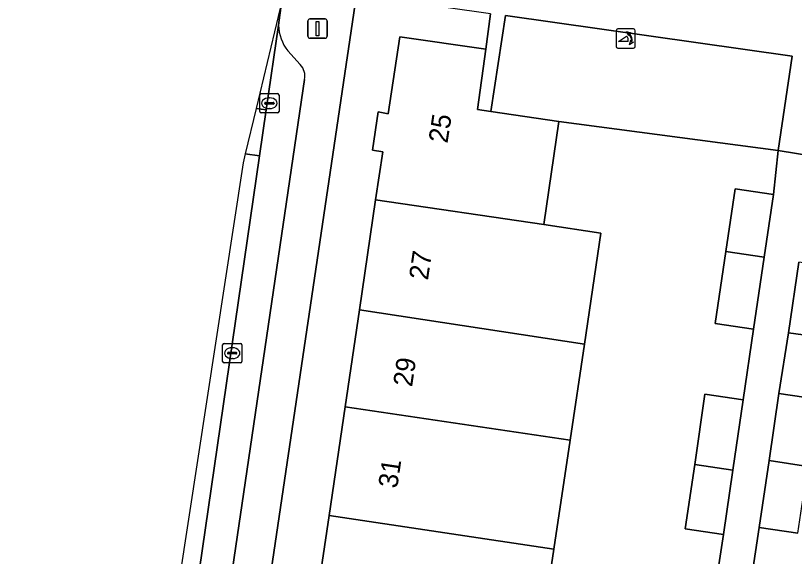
# Model space of a CAD drawing. Extents: x 164148 to 165261, y 382513 to 383432.
# Drawn here: x 164207.73 to 164248.11, y 382965.61 to 382993.68 of the extents above; entities that cross this region are included whole.
import ezdxf

# ---------------------------------------------------------------- set-up
doc = ezdxf.new("R2010")
doc.units = 0
for name, color, linetype in [('IMGEO_Erf', 7, 'Continuous'), ('IMGEO_Kolk', 7, 'Continuous'), ('IMGEO_Lichtmast', 7, 'Continuous'), ('IMGEO_Pand', 7, 'Continuous'), ('IMGEO_Pand_nummerreeks', 7, 'Continuous'), ('IMGEO_Parkeervlak_open', 7, 'Continuous'), ('IMGEO_Poller', 7, 'Continuous'), ('IMGEO_Rijbaan_lokaal_gesloten', 7, 'Continuous'), ('IMGEO_Rijbaan_lokaal_open', 7, 'Continuous'), ('IMGEO_Voetpad_open', 7, 'Continuous')]:
    doc.layers.add(name, color=color, linetype=linetype)

msp = doc.modelspace()

# ---------------------------------------------------------------- linework, layer by layer
at = {"layer": 'IMGEO_Erf'}
msp.add_lwpolyline([(164223.194, 382962.384), (164223.982, 382967.727), (164224.814, 382973.374), (164225.557, 382978.411), (164226.399, 382984.12), (164226.766, 382986.613), (164226.242, 382986.692), (164226.538, 382988.678), (164227.056, 382988.575), (164227.652, 382992.573), (164232.112, 382991.925), (164232.356, 382993.76), (164225.405, 382994.767), (164218.335, 382947.025), (164225.294, 382945.995), (164225.622, 382947.869), (164221.151, 382948.522), (164221.738, 382952.502), (164221.214, 382952.579), (164221.507, 382954.563), (164222.031, 382954.492), (164222.436, 382957.239)], close=True, dxfattribs=at)
for points in [[(164243.867, 382963.027), (164244.432, 382966.748), (164242.453, 382967.035), (164242.939, 382970.38), (164243.468, 382974.022), (164245.448, 382973.734), (164245.986, 382977.397), (164244.007, 382977.691), (164244.562, 382981.432), (164245.046, 382984.689), (164247.024, 382984.396), (164247.26, 382986.674), (164235.9, 382988.175), (164235.114, 382982.83), (164238.076, 382982.393), (164237.235, 382976.626), (164236.488, 382971.649), (164235.639, 382965.995), (164234.838, 382960.655)], [(164249.829, 382976.93), (164247.812, 382977.22), (164247.307, 382974.069), (164249.315, 382973.774)], [(164248.292, 382966.82), (164246.284, 382967.115), (164245.907, 382964.58), (164247.915, 382964.284), (164247.398, 382960.779), (164246.889, 382957.328), (164244.881, 382957.624), (164244.553, 382955.398), (164246.557, 382955.102), (164246.026, 382951.547), (164245.485, 382947.932), (164243.495, 382948.226), (164243.081, 382945.579), (164245.089, 382945.283), (164244.566, 382941.738), (164244.062, 382938.318)]]:
    msp.add_lwpolyline(points, dxfattribs=at)
at = {"layer": 'IMGEO_Kolk'}
for p, q in [((164220.388, 382988.7), (164220.388, 382989.552)), ((164220.463, 382989.626), (164221.315, 382989.626)), ((164220.876, 382989.406), (164220.901, 382989.406)), ((164221.389, 382989.552), (164221.389, 382988.7)), ((164220.647, 382989.12), (164220.647, 382989.132)), ((164221.085, 382989.083), (164220.687, 382989.083)), ((164220.69, 382989.169), (164221.088, 382989.169)), ((164220.899, 382988.846), (164220.874, 382988.846)), ((164221.131, 382989.132), (164221.131, 382989.12)), ((164221.315, 382988.626), (164220.463, 382988.626)), ((164218.462, 382975.732), (164218.462, 382976.584)), ((164218.537, 382976.658), (164219.389, 382976.658)), ((164218.95, 382976.438), (164218.975, 382976.438)), ((164219.463, 382976.584), (164219.463, 382975.732)), ((164218.721, 382976.152), (164218.721, 382976.164)), ((164219.159, 382976.115), (164218.761, 382976.115)), ((164218.764, 382976.201), (164219.162, 382976.201)), ((164219.205, 382976.164), (164219.205, 382976.152)), ((164219.389, 382975.658), (164218.537, 382975.658)), ((164218.973, 382975.878), (164218.948, 382975.878))]:
    msp.add_line(p, q, dxfattribs=at)
for points in [[(164220.388, 382988.7), (164220.388, 382989.552)], [(164220.463, 382989.626), (164221.315, 382989.626)], [(164221.389, 382989.552), (164221.389, 382988.7)], [(164221.315, 382988.626), (164220.463, 382988.626)], [(164218.462, 382975.732), (164218.462, 382976.584)], [(164218.537, 382976.658), (164219.389, 382976.658)], [(164219.463, 382976.584), (164219.463, 382975.732)], [(164219.389, 382975.658), (164218.537, 382975.658)]]:
    msp.add_lwpolyline(points, dxfattribs=at)
for centre, radius, start, end in [((164220.465, 382989.55), 0.0765, 91.552, 178.448), ((164220.465, 382989.55), 0.0765, 91.552, 178.448), ((164221.313, 382989.55), 0.0765, 1.552, 88.448), ((164221.313, 382989.55), 0.0765, 1.552, 88.448), ((164220.687, 382989.129), 0.0403, 85.8775, 175.7526), ((164220.684, 382989.119), 0.0366, 178.938, 274.7102), ((164221.088, 382989.126), 0.043, 264.8664, 352.4533), ((164221.092, 382989.131), 0.0386, 1.7309, 96.639), ((164220.465, 382988.702), 0.0765, 181.552, 268.448), ((164220.465, 382988.702), 0.0765, 181.552, 268.448), ((164221.313, 382988.702), 0.0765, 271.552, 358.448), ((164221.313, 382988.702), 0.0765, 271.552, 358.448), ((164218.539, 382976.582), 0.0765, 91.552, 178.448), ((164218.539, 382976.582), 0.0765, 91.552, 178.448), ((164219.387, 382976.582), 0.0765, 1.552, 88.448), ((164219.387, 382976.582), 0.0765, 1.552, 88.448), ((164218.761, 382976.161), 0.0403, 85.8775, 175.7526), ((164218.758, 382976.151), 0.0366, 178.938, 274.7102), ((164219.162, 382976.158), 0.043, 264.8664, 352.4533), ((164219.166, 382976.163), 0.0386, 1.7309, 96.639), ((164218.539, 382975.734), 0.0765, 181.552, 268.448), ((164218.539, 382975.734), 0.0765, 181.552, 268.448), ((164219.387, 382975.734), 0.0765, 271.552, 358.448), ((164219.387, 382975.734), 0.0765, 271.552, 358.448)]:
    msp.add_arc(centre, radius, start, end, dxfattribs=at)
for centre, major_axis, ratio, start_param, end_param in [((164220.875, 382989.126), (-0.387, 0.002), 0.722429, 4.712389, 7.853982), ((164220.9, 382989.126), (-0.39, 0.002), 0.717154, 1.570796, 4.712389), ((164218.949, 382976.158), (-0.387, 0.002), 0.722429, 4.712389, 7.853982), ((164218.974, 382976.158), (-0.39, 0.002), 0.717154, 1.570796, 4.712389)]:
    msp.add_ellipse(centre, major_axis=major_axis, ratio=ratio, start_param=start_param, end_param=end_param, dxfattribs=at)
at = {"layer": 'IMGEO_Lichtmast'}
for p, q in [((164222.89, 382992.599), (164222.89, 382993.399)), ((164222.89, 382993.399), (164222.89, 382992.599)), ((164222.99, 382993.499), (164223.78, 382993.499)), ((164223.78, 382993.499), (164222.99, 382993.499)), ((164223.88, 382993.399), (164223.88, 382992.599)), ((164223.88, 382992.599), (164223.88, 382993.399)), ((164223.78, 382992.499), (164222.99, 382992.499)), ((164222.99, 382992.499), (164223.78, 382992.499))]:
    msp.add_line(p, q, dxfattribs=at)
msp.add_lwpolyline([(164223.31, 382993.374), (164223.46, 382993.374), (164223.46, 382992.624), (164223.31, 382992.624), (164223.31, 382993.374)], dxfattribs=at)
for centre, start, end in [((164222.99, 382993.399), 90, 180), ((164222.99, 382993.399), 90, 180), ((164223.78, 382993.399), 0, 90), ((164223.78, 382993.399), 360, 90), ((164222.99, 382992.599), 180, 270), ((164222.99, 382992.599), 180, 270), ((164223.78, 382992.599), 270, 0), ((164223.78, 382992.599), 270, 0)]:
    msp.add_arc(centre, 0.1, start, end, dxfattribs=at)
at = {"layer": 'IMGEO_Pand'}
for points in [[(164235.114, 382982.83), (164235.9, 382988.175), (164232.367, 382988.7), (164231.678, 382988.803), (164232.112, 382991.925), (164227.652, 382992.573), (164227.056, 382988.575), (164226.538, 382988.678), (164226.242, 382986.692), (164226.766, 382986.613), (164226.399, 382984.12)], [(164244.562, 382981.432), (164246.541, 382981.139), (164247.024, 382984.396), (164245.046, 382984.689)], [(164235.114, 382982.83), (164226.399, 382984.12), (164225.557, 382978.411), (164237.235, 382976.626), (164238.076, 382982.393)], [(164244.562, 382981.432), (164244.007, 382977.691), (164245.986, 382977.397), (164246.541, 382981.139)], [(164248.34, 382980.884), (164247.812, 382977.22), (164249.829, 382976.93), (164250.355, 382980.586)], [(164224.814, 382973.374), (164236.488, 382971.649), (164237.235, 382976.626), (164225.557, 382978.411)], [(164244.917, 382970.087), (164245.448, 382973.734), (164243.468, 382974.022), (164242.939, 382970.38)], [(164246.793, 382970.58), (164248.801, 382970.283), (164249.315, 382973.774), (164247.307, 382974.069)], [(164223.982, 382967.727), (164235.639, 382965.995), (164236.488, 382971.649), (164224.814, 382973.374)], [(164244.917, 382970.087), (164242.939, 382970.38), (164242.453, 382967.035), (164244.432, 382966.748)], [(164246.793, 382970.58), (164246.284, 382967.115), (164248.292, 382966.82), (164248.801, 382970.283)], [(164223.982, 382967.727), (164223.194, 382962.384), (164231.893, 382961.097), (164234.838, 382960.655), (164235.639, 382965.995)]]:
    msp.add_lwpolyline(points, close=True, dxfattribs=at)
at = {"layer": 'IMGEO_Parkeervlak_open'}
msp.add_lwpolyline([(164235.9, 382988.175), (164247.26, 382986.674), (164248.002, 382991.565), (164233.128, 382993.672), (164232.367, 382988.7)], close=True, dxfattribs=at)
for points in [[(164221.367, 382993.179), (164220.727, 382988.779), (164220.382, 382986.403), (164215.997, 382956.251), (164215.016, 382950.356)], [(164222.49, 382991.13), (164221.842, 382991.842)], [(164217.182, 382952.744), (164222.71, 382990.351)]]:
    msp.add_lwpolyline(points, dxfattribs=at)
for centre, radius, start, end in [((164223.587, 382993.215), 2.22, 180.9224, 218.1951), ((164221.882, 382990.538), 0.849, 347.2815, 44.2592)]:
    msp.add_arc(centre, radius, start, end, dxfattribs=at)
at = {"layer": 'IMGEO_Poller'}
for p, q in [((164238.861, 382992.885), (164238.861, 382992.078)), ((164238.861, 382992.885), (164238.861, 382992.078)), ((164239.763, 382992.98), (164238.955, 382992.98)), ((164239.763, 382992.98), (164238.955, 382992.98)), ((164239.857, 382992.078), (164239.857, 382992.885)), ((164239.857, 382992.078), (164239.857, 382992.885)), ((164238.955, 382991.983), (164239.763, 382991.983)), ((164238.955, 382991.983), (164239.763, 382991.983))]:
    msp.add_line(p, q, dxfattribs=at)
for points in [[(164239.496, 382992.336), (164238.983, 382992.336), (164239.413, 382992.611)], [(164239.54, 382992.709), (164239.528, 382992.636), (164239.403, 382992.841)], [(164239.403, 382992.841), (164239.634, 382992.775), (164239.563, 382992.743)], [(164239.556, 382992.164), (164239.622, 382992.395), (164239.652, 382992.327)], [(164239.688, 382992.3), (164239.76, 382992.289), (164239.556, 382992.164)]]:
    msp.add_lwpolyline(points, dxfattribs=at)
for centre, radius, start, end in [((164238.955, 382992.885), 0.0946, 90, 180), ((164238.955, 382992.885), 0.0946, 90, 180), ((164239.763, 382992.885), 0.0946, 0, 90), ((164239.763, 382992.885), 0.0946, 0, 90), ((164239.168, 382992.386), 0.332, 351.3247, 42.4854), ((164239.182, 382992.396), 0.476, 351.7527, 41.1691), ((164239.182, 382992.396), 0.516, 349.3569, 42.2912), ((164238.955, 382992.078), 0.0946, 180, 270), ((164238.955, 382992.078), 0.0946, 180, 270), ((164239.763, 382992.078), 0.0946, 270, 0), ((164239.763, 382992.078), 0.0946, 270, 0)]:
    msp.add_arc(centre, radius, start, end, dxfattribs=at)
at = {"layer": 'IMGEO_Rijbaan_lokaal_gesloten'}
for points in [[(164220.204, 382988.86), (164220.727, 382988.779), (164221.367, 382993.179), (164221.518, 382994.343), (164221.531, 382994.431)], [(164207.73, 382909.028), (164208.846, 382908.867), (164209.891, 382915.383), (164213.125, 382937.491), (164213.601, 382940.634), (164214.786, 382948.788), (164215.016, 382950.356), (164215.997, 382956.251), (164220.382, 382986.403), (164219.642, 382986.502), (164219.529, 382986.027)]]:
    msp.add_lwpolyline(points, close=True, dxfattribs=at)
at = {"layer": 'IMGEO_Rijbaan_lokaal_open'}
for points in [[(164232.356, 382993.76), (164232.112, 382991.925), (164231.678, 382988.803), (164232.367, 382988.7), (164233.128, 382993.672), (164248.002, 382991.565), (164247.26, 382986.674), (164249.057, 382986.385), (164249.772, 382991.276), (164264.768, 382989.02), (164264.054, 382984.022), (164264.753, 382983.919), (164265.229, 382987.03), (164265.514, 382988.929), (164272.503, 382987.831), (164273.356, 382993.681)], [(164220.204, 382988.86), (164219.642, 382986.502), (164220.382, 382986.403), (164220.727, 382988.779), (164220.204, 382988.86)]]:
    msp.add_lwpolyline(points, dxfattribs=at)
at = {"layer": 'IMGEO_Voetpad_open'}
for points in [[(164210.279, 382903.562), (164211.978, 382914.419), (164213.147, 382915.203), (164213.683, 382915.563), (164217.484, 382941.376), (164217.838, 382943.705), (164218.335, 382947.025), (164225.405, 382994.767), (164226.244, 383000.61), (164230.145, 383026.845), (164230.722, 383030.829), (164231.418, 383035.873), (164232.031, 383039.843), (164234.511, 383056.705), (164234.719, 383058.116), (164235.668, 383064.759), (164235.932, 383066.495), (164233.89, 383059.255), (164229.135, 383026.35), (164226.28, 383014.365), (164225.082, 383006.058)], [(164224.03, 383004.922), (164223.345, 383002.046), (164223.699, 383002.004), (164222.54, 382994.192), (164221.518, 382994.343), (164221.367, 382993.179)], [(164221.842, 382991.842), (164222.49, 382991.13)], [(164222.71, 382990.351), (164217.182, 382952.744)], [(164249.057, 382986.385), (164247.26, 382986.674), (164247.024, 382984.396), (164246.541, 382981.139), (164245.986, 382977.397), (164245.448, 382973.734), (164244.917, 382970.087), (164244.432, 382966.748), (164243.867, 382963.027)], [(164245.907, 382964.58), (164246.284, 382967.115), (164246.793, 382970.58), (164247.307, 382974.069), (164247.812, 382977.22), (164248.34, 382980.884)]]:
    msp.add_lwpolyline(points, dxfattribs=at)
for centre, radius, start, end in [((164223.587, 382993.215), 2.22, 180.9224, 218.1951), ((164221.882, 382990.538), 0.849, 347.2815, 44.2592)]:
    msp.add_arc(centre, radius, start, end, dxfattribs=at)

# ---------------------------------------------------------------- texts
at = {"layer": 'IMGEO_Pand_nummerreeks'}
for s, rotation, p in [('25', 81.3646, (164230.121, 382987.017)), ('27', 81.5592, (164229.107, 382979.912)), ('29', 81.6774, (164228.286, 382974.378)), ('31', 81.5257, (164227.513, 382969.112))]:
    msp.add_text(s, height=1, rotation=rotation, dxfattribs=at).set_placement(p)

doc.saveas('drawing.dxf')
